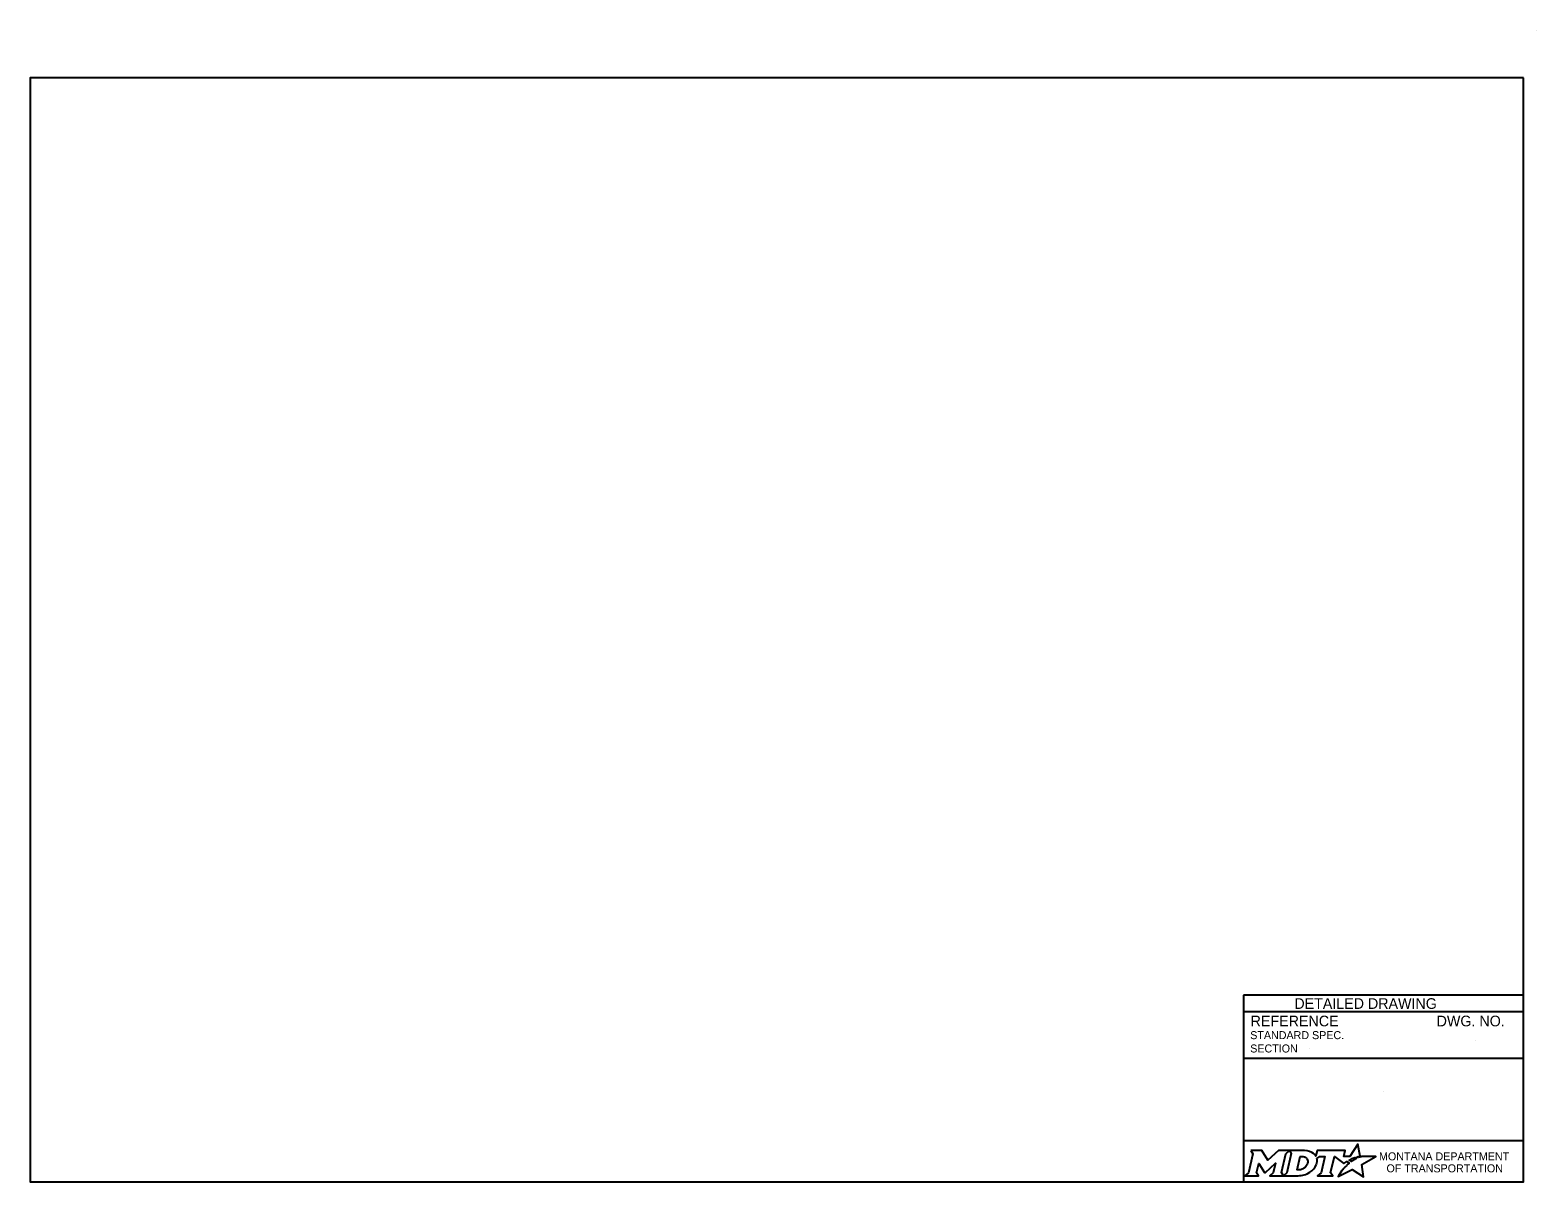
# Model space of a CAD drawing. Extents: x 49991.4 to 50021, y 49987.6 to 50011.4.
# Drawn here: x 50009.74 to 50021.04, y 49999.89 to 50008.52 of the extents above; entities that cross this region are included whole.
import ezdxf

# ---------------------------------------------------------------- set-up
doc = ezdxf.new("R2010")
doc.units = 0
for name, color, linetype in [('Default', 7, 'Continuous'), ('Level 1', 7, 'Continuous'), ('Level 4', 7, 'Continuous')]:
    doc.layers.add(name, color=color, linetype=linetype)

msp = doc.modelspace()

# ---------------------------------------------------------------- linework, layer by layer
at = {"layer": 'Default'}
for points in [[(50019.7, 50000.068), (50019.69, 50000.074), (50019.702, 50000.076), (50019.713, 50000.078), (50019.696, 50000.168), (50019.636, 50000.077), (50019.589, 50000.076), (50019.599, 50000.12), (50019.39, 50000.121), (50019.38, 50000.078), (50019.374, 50000.086)], [(50018.893, 50000.121), (50018.907, 50000.097), (50018.874, 49999.954), (50018.848, 49999.931), (50018.95, 49999.931), (50018.936, 49999.954), (50018.952, 50000.024), (50018.996, 49999.955), (50019.002, 49999.955), (50019.077, 50000.025), (50019.06, 49999.954), (50019.035, 49999.932), (50019.137, 49999.932), (50019.123, 49999.955), (50019.156, 50000.097)], [(50019.156, 50000.097), (50019.182, 50000.121), (50019.099, 50000.121), (50019.02, 50000.048), (50018.975, 50000.12), (50018.893, 50000.121)], [(50019.295, 50000.121), (50019.182, 50000.121), (50019.196, 50000.098), (50019.163, 49999.954), (50019.137, 49999.932), (50019.248, 49999.932)], [(50019.319, 50000.034), (50019.318, 50000.026), (50019.315, 50000.017), (50019.311, 50000.008), (50019.305, 50000.001), (50019.299, 49999.994), (50019.291, 49999.988), (50019.282, 49999.983), (50019.273, 49999.979), (50019.264, 49999.977), (50019.255, 49999.976), (50019.239, 49999.976), (50019.263, 50000.076), (50019.279, 50000.076), (50019.286, 50000.075), (50019.294, 50000.073), (50019.301, 50000.07), (50019.307, 50000.066), (50019.311, 50000.061), (50019.315, 50000.055), (50019.318, 50000.049), (50019.319, 50000.042), (50019.32, 50000.038), (50019.319, 50000.034)], [(50019.387, 50000.062), (50019.411, 50000.075), (50019.448, 50000.075), (50019.42, 49999.954), (50019.392, 49999.931), (50019.508, 49999.931), (50019.491, 49999.954), (50019.52, 50000.075), (50019.591, 50000.023), (50019.612, 50000.038), (50019.632, 50000.027)], [(50019.576, 49999.971), (50019.561, 49999.947), (50019.556, 49999.939), (50019.55, 49999.931), (50019.548, 49999.926), (50019.653, 49999.979), (50019.737, 49999.924), (50019.724, 50000.017), (50019.831, 50000.075), (50019.782, 50000.076), (50019.751, 50000.077), (50019.731, 50000.077), (50019.724, 50000.075), (50019.719, 50000.074), (50019.711, 50000.072), (50019.7, 50000.068)], [(50019.65, 50000.04), (50019.648, 50000.039), (50019.629, 50000.048), (50019.639, 50000.054), (50019.644, 50000.056), (50019.652, 50000.06), (50019.658, 50000.063), (50019.666, 50000.066), (50019.673, 50000.068), (50019.685, 50000.061), (50019.681, 50000.059), (50019.676, 50000.056), (50019.672, 50000.054), (50019.667, 50000.051), (50019.665, 50000.05), (50019.662, 50000.049), (50019.66, 50000.047), (50019.658, 50000.046), (50019.655, 50000.044), (50019.652, 50000.042), (50019.65, 50000.04)], [(50019.293, 49999.939), (50019.302, 49999.942), (50019.315, 49999.947), (50019.335, 49999.958)], [(50019.59, 49999.987), (50019.59, 49999.987)]]:
    msp.add_lwpolyline(points, dxfattribs=at)
for centre, radius, start, end in [((50019.319, 50000.042), 0.0709, 339.5329, 15.8582), ((50019.274, 50000.059), 0.118, 300.9103, 339.1383)]:
    msp.add_arc(centre, radius, start, end, dxfattribs=at)
for centre, major_axis, ratio, start_param, end_param in [((50019.293, 50000.073), (0.0834, -0.0037), 0.568097, 0.61298, 1.570796), ((50019.349, 50000.081), (0.0361, -0.0295), 0.469099, 1.225588, 1.570796), ((50019.621, 50000.017), (-0.0112, -0.0097), 0.021651, 3.157348, 6.283185), ((50019.248, 50000.08), (0, 0.148), 0.987302, 3.139398, 3.456847), ((50019.583, 49999.979), (-0.00694, -0.00806), 0.008222, 0, 3.137361), ((50019.6, 49999.997), (-0.0098, -0.0102), 0.016458, 3.141593, 6.279097)]:
    msp.add_ellipse(centre, major_axis=major_axis, ratio=ratio, start_param=start_param, end_param=end_param, dxfattribs=at)
at = {"layer": 'Level 1'}
msp.add_line((50021.038, 50008.524), (50021.038, 50008.524), dxfattribs=at)
msp.add_lwpolyline([(50020.938, 50008.165), (50009.737, 50008.165), (50009.737, 49999.886), (50020.938, 49999.886)], close=True, dxfattribs=at)
at = {"layer": 'Level 4'}
for p, q in [((50020.938, 50001.286), (50018.838, 50001.286)), ((50018.838, 50001.286), (50018.838, 49999.886)), ((50020.938, 50001.161), (50018.838, 50001.161)), ((50020.574, 50000.946), (50020.574, 50000.946)), ((50020.938, 50000.811), (50018.838, 50000.811)), ((50019.332, 50000.886), (50019.332, 50000.886)), ((50019.888, 50000.562), (50019.888, 50000.562)), ((50020.938, 50000.193), (50018.838, 50000.193))]:
    msp.add_line(p, q, dxfattribs=at)

# ---------------------------------------------------------------- texts
at = {"layer": 'Default'}
for s, p in [('MONTANA DEPARTMENT', (50019.854, 50000.047)), ('OF TRANSPORTATION', (50019.91, 49999.957))]:
    msp.add_text(s, height=0.06, dxfattribs=at).set_placement(p)
at = {"layer": 'Level 4'}
for s, height, p in [('DETAILED DRAWING', 0.0799, (50019.219, 50001.183)), ('REFERENCE', 0.08, (50018.891, 50001.052)), ('DWG. NO.', 0.08, (50020.286, 50001.052)), ('STANDARD SPEC.', 0.06, (50018.888, 50000.956)), ('SECTION', 0.06, (50018.888, 50000.856))]:
    msp.add_text(s, height=height, dxfattribs=at).set_placement(p)

doc.saveas('drawing.dxf')
